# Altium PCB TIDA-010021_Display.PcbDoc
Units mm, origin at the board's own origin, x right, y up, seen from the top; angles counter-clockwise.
Board outline 36.07 x 41.91 mm, 2 copper layers (Top Layer, Bottom Layer), stack 1.575 mm thick; 46 components, 36 nets, 172 pads, 45 vias.
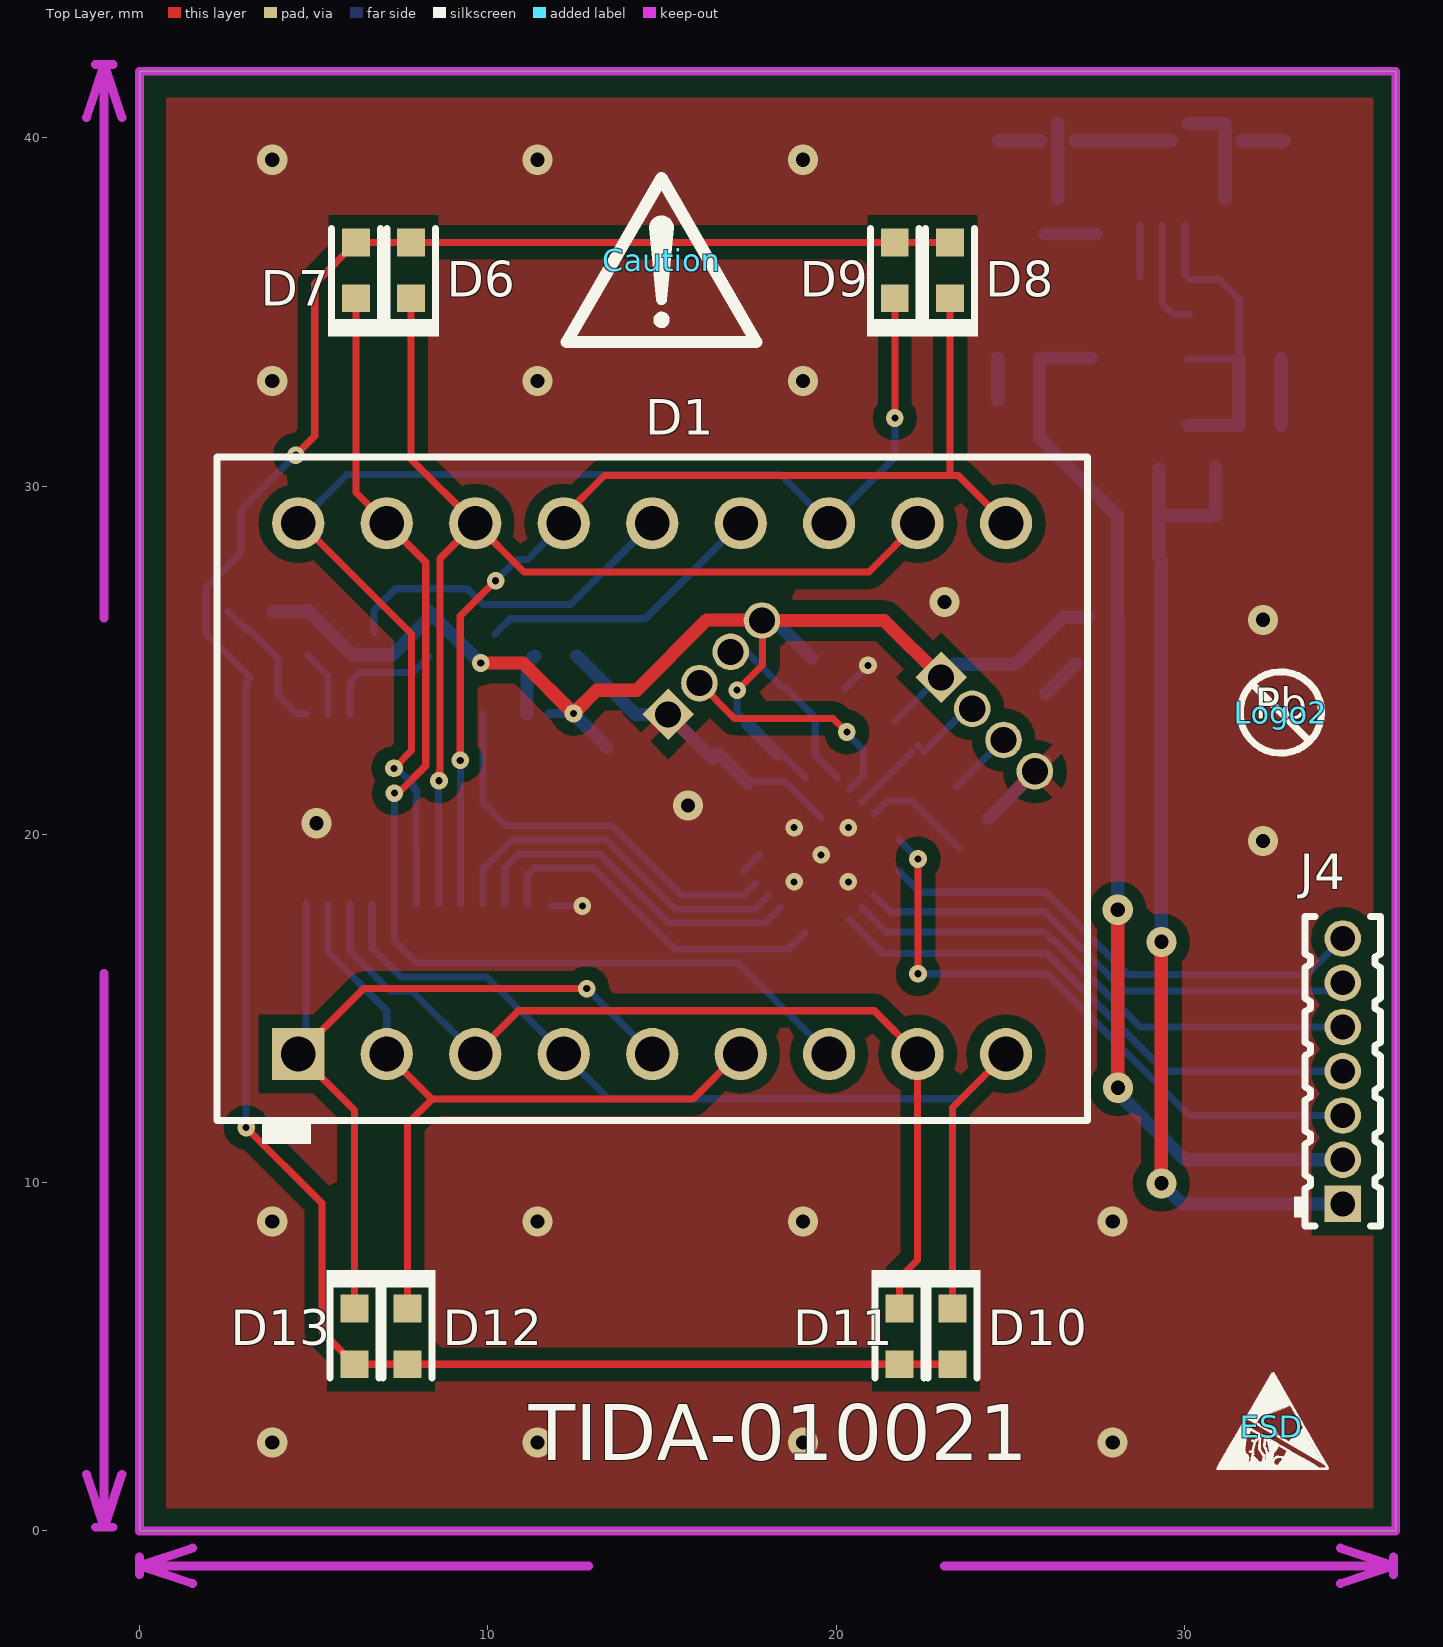
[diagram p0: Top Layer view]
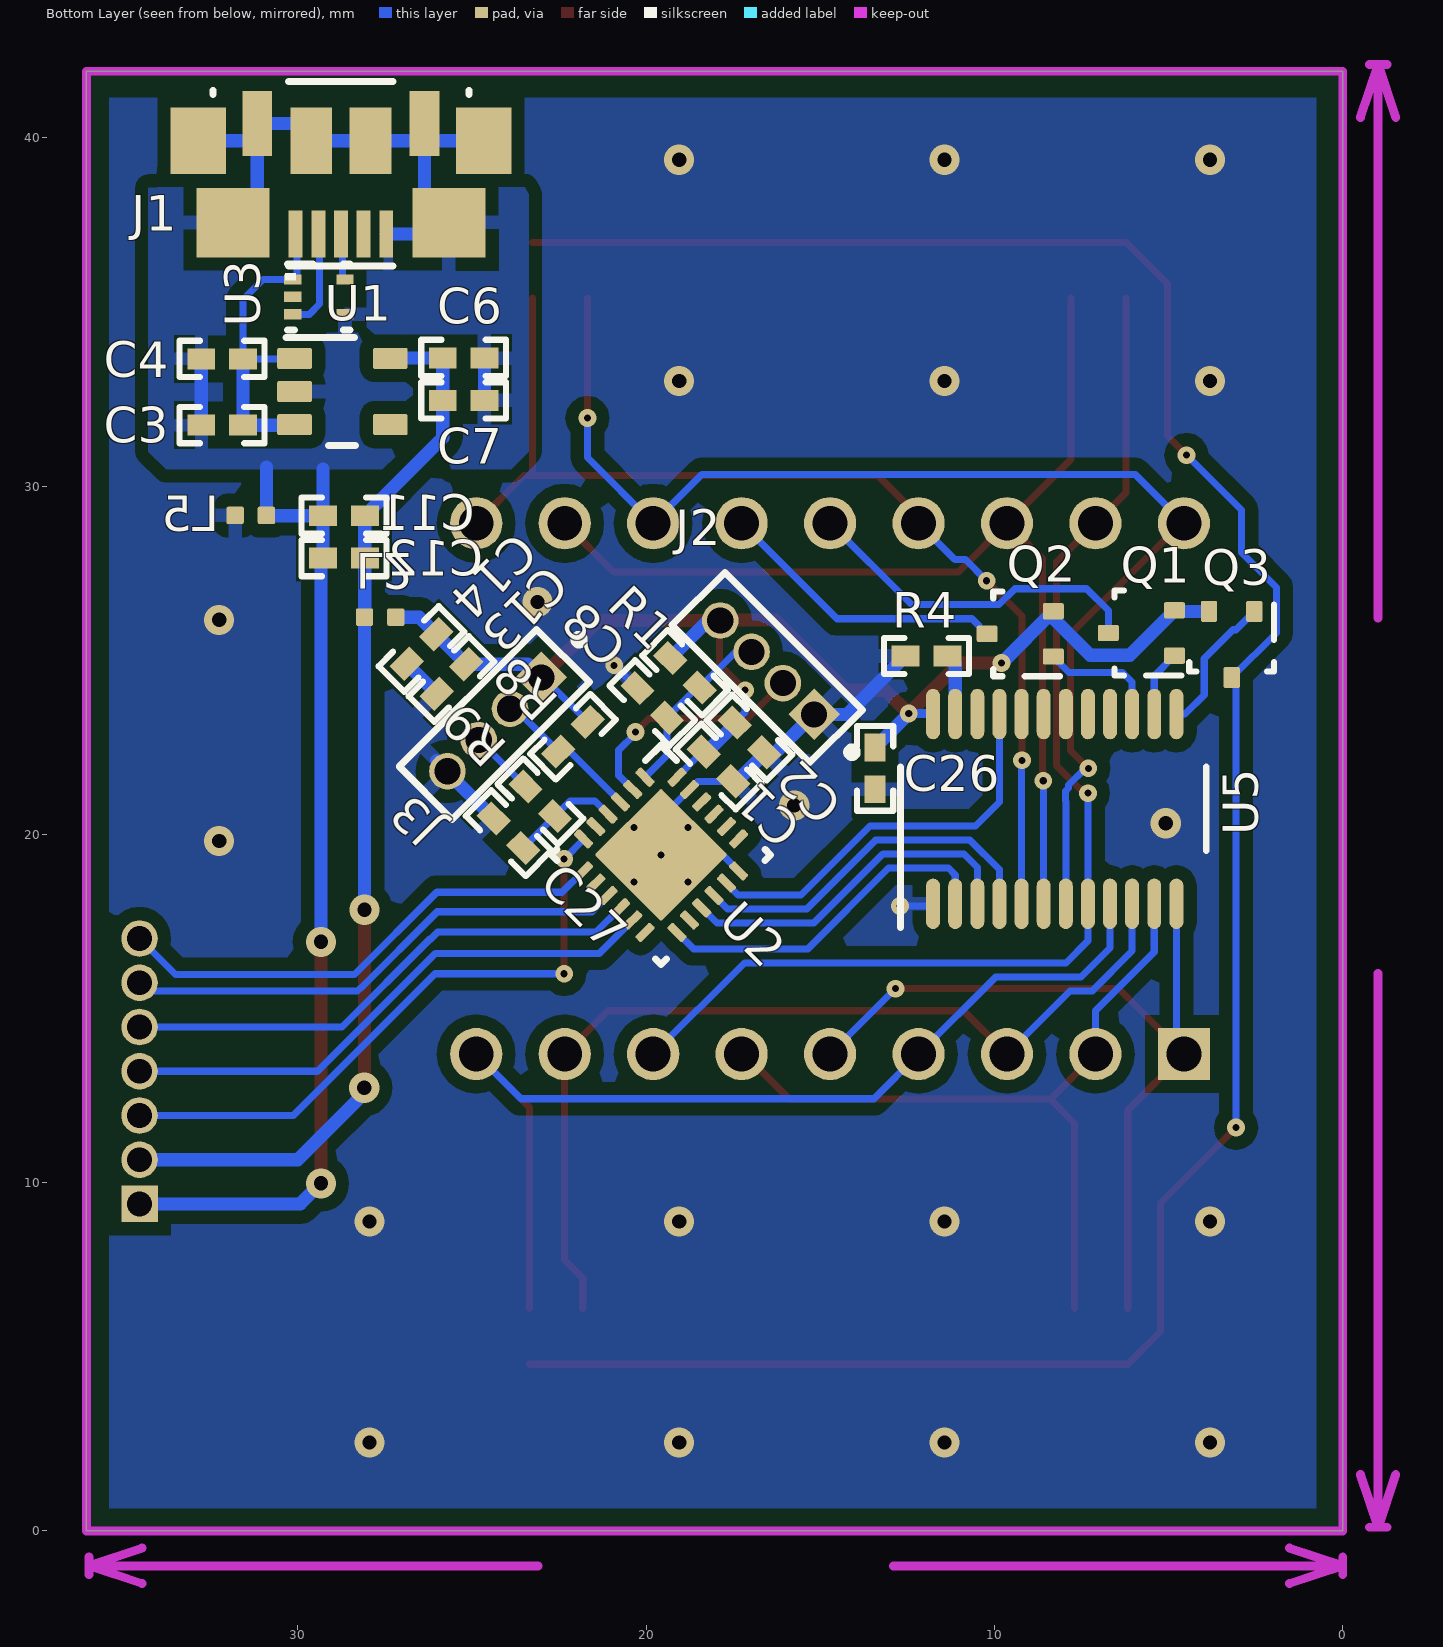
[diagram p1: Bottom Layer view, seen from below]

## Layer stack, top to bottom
Top Solder: solder mask 0.0102, Solder Resist, Dk 3.5
Top Layer: signal copper 0.0356
Dielectric1: core 1.5037, FR-4, Dk 4.8
Bottom Layer: signal copper 0.0356
Bottom Solder: solder mask 0.0102, Solder Resist, Dk 3.5

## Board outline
0,0 0,41.91 36.068,41.91 36.068,0

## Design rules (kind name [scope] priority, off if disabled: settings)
AcuteAngle [All] p1: minimum=4.50000000000000E+0001 checktracksonly=FALSE
AssemblyTestPointUsage [All] p1: valid=2
BoardOutlineClearance BoardOutlineClearance_MountingHoles [OnCopper and InComponentClass('Mounting Holes')] p1: gap=1.016
BoardOutlineClearance BoardOutlineClearance_Poly [OnCopper and IsPoly] p2: gap=0.635
BoardOutlineClearance [OnCopper and Not InComponentClass('Logo') and not InComponentClass('FiducialMark') and not InRegion(1000,500,4000,800) and not InPoly] p3: gap=1.905
Clearance Clearance_Keepouts [((IsTrack Or IsArc) And Not InPoly) And IsFree and IsKeepOut vs ((IsTrack Or IsArc) And Not InPoly) And IsFree and IsKeepOut] p1: gap=0
Clearance Clearance_Poly [InPolygon] p2: gap=0.381
Clearance [All] p3: gap=0.2
ComponentClearance ComponentClearance_MountingHoles_FiducialMarks [InComponentClass('Mounting Holes') vs InComponentClass('FiducialMark')] p1: gap=1.27 collisioncheckmode=3 verticalgap=0.254 showdistances=FALSE
ComponentClearance ComponentClearance_Shunt [InComponentClass('Header') vs InComponentClass('Shunt')] p2: gap=0 collisioncheckmode=3 verticalgap=0 showdistances=FALSE
ComponentClearance ComponentClearance_Logo [InComponentClass('Logo')] p3: gap=1.27 collisioncheckmode=3 verticalgap=0.254 showdistances=FALSE
ComponentClearance ComponentClearance_ScrewToNut [(HasFootprint('NY PMS 440 0025 PH')) vs (HasFootprint('Keystone_1902C'))] p4: gap=0.127 collisioncheckmode=3 verticalgap=0.254 showdistances=FALSE
ComponentClearance ComponentClearance_MountingHoles [InComponentClass('Mounting Holes')] p5: gap=6.35 collisioncheckmode=3 verticalgap=2540 showdistances=FALSE
ComponentClearance ComponentClearance_SmallPassives [HasFootprint('0201*') or HasFootprint('0402*') or HasFootprint('0508') or HasFootprint('0603*') or HasFootprint('0612') or HasFootprint('0805*') or HasFootprint('0815*') or HasFootprint('0830*') or HasFootprint('1206*') or HasFootprint('1210*') or HasFootprint('1808*') or HasFootprint('1812*') or HasFootprint('1825*') or HasFootprint('2010*') or HasFootprint('2220*') or HasFootprint('2225*') or HasFootprint('2512*') or HasFootprint('2728*') or HasFootprint('3518*') vs HasFootprint('0201*') or HasFootprint('0402*') or HasFootprint('0508') or HasFootprint('0603*') or HasFootprint('0612') or HasFootprint('0805*') or HasFootprint('0815*') or HasFootprint('0830*') or HasFootprint('1206*') or HasFootprint('1210*') or HasFootprint('1808*') or HasFootprint('1812*') or HasFootprint('1825*') or HasFootprint('2010*') or HasFootprint('2220*') or HasFootprint('2225*') or HasFootprint('2512*') or HasFootprint('2728*') or HasFootprint('3518*')] p6: gap=0.38 collisioncheckmode=3 verticalgap=0.254 showdistances=FALSE
ComponentClearance ComponentClearance_THtoSMT [IsThruComponent vs IsSMTComponent] p7: gap=1.016 collisioncheckmode=3 verticalgap=0.762 showdistances=FALSE
ComponentClearance ComponentClearance_THtoTH [IsThruComponent vs IsThruComponent] p8: gap=0.762 collisioncheckmode=3 verticalgap=0.762 showdistances=FALSE
ComponentClearance [All] p9: gap=0.762 collisioncheckmode=3 verticalgap=0.254 showdistances=FALSE
DiffPairsRouting [All] p1: maxlimit=2.54 minlimit=0.254 mostfreqgap=0.254 toplayer_minwidth=0.381 toplayer_maxwidth=0.381 toplayer_prefwidth=0.381 bottomlayer_minwidth=0.381 bottomlayer_maxwidth=0.381 bottomlayer_prefwidth=0.381 maxuncoupledlength=25.4
FabricationTestPointUsage TestPointUsage [All] p1: valid=2 allowmultiple=FALSE
FabricationTestpoint Testpoint [All] p1: side=3 testpointundercomponent=TRUE minsize=1.016 maxsize=2.54 preferedsize=1.524 minholesize=0 maxholesize=1.016 preferedholesize=0.813 testpointgrid=0.025 allowsidetop=TRUE allowsidebottom=TRUE usegrid=TRUE gridtolerance=0
FanoutControl Fanout_LCC [IsLCC] p1: bgadir=Out bgaviamode=Centered fanoutstyle=Auto fanoutdirection=Alternating viagrid=0.025 // Fanout_LCC (Default Rule)
FanoutControl Fanout_BGA [IsBGA] p2: bgadir=Out bgaviamode=Centered fanoutstyle=Auto fanoutdirection=Alternating viagrid=0.025 // Fanout_BGA (Default Rule)
FanoutControl Fanout_Default [All] p4: bgadir=Out bgaviamode=Centered fanoutstyle=Auto fanoutdirection=Alternating viagrid=0.025 // Fanout_Default (Default Rule)
FanoutControl Fanout_Small [(CompPinCount < 5)] p5: bgadir=Out bgaviamode=Centered fanoutstyle=Auto fanoutdirection=OutThenIn viagrid=0.025 // Fanout_Small (Default Rule)
HoleSize [All] p1: absolutevalues=TRUE maxlimit=6.375 minlimit=0.2 maxpercent=80.000 minpercent=20.000
MinimumAnnularRing MinimumAnnularRing_ThermalPadVias [IsVia and InAnyComponent] p1: minimumring=0.15
MinimumAnnularRing [All] p2: minimumring=0.203
MinimumSolderMaskSliver MinimumSolderMaskSliver_Logo [InComponentClass('Logo') vs InComponentClass('Logo')] p1: minsoldermaskwidth=0.018
MinimumSolderMaskSliver [All] p2: minsoldermaskwidth=0.1
PlaneClearance [All] p1: clearance=0.381
PlaneConnect [All] p1: planeconnectstyle=Relief reliefexpansion=0.254 reliefentries=4 reliefconductorwidth=0.381 reliefairgap=0.381
PolygonConnect PolygonConnect_Via [IsVia] p1: connectstyle=Direct reliefconductorwidth=0.254 reliefentries=4 polygonreliefangle="90 Angle" airgapwidth=0.254
PolygonConnect [IsComponentPad] p2: connectstyle=Relief reliefconductorwidth=0.381 reliefentries=4 polygonreliefangle="90 Angle" airgapwidth=0.381
RoutingVias ThermalPadVias [IsVia and InAnyComponent] p1: holewidth=0.2 width=0.5 viastyle="Through Hole" minholewidth=0.2 minwidth=0.5 maxholewidth=0.33 maxwidth=0.6
RoutingVias [All] p2: holewidth=0.406 width=0.864 viastyle="Through Hole" minholewidth=0.2 minwidth=0.66 maxholewidth=1.016 maxwidth=1.651
SilkToBoardRegionClearance [Not ((IsComment or IsDesignator) And (Hide <> 'False')) and not InRegion(1000,500,4000,800)] p1:
SilkToSilkClearance SilkToSilkClearance_Pb-FreeLogo [(HasFootprint('Pb-Free_Overlay_Medium') OR HasFootprint('Pb-Free_Overlay_Small')) vs (HasFootprint('Pb-Free_Overlay_Medium') OR HasFootprint('Pb-Free_Overlay_Small'))] p1: silktosilkclearance=0
SilkToSilkClearance [All] p2: silktosilkclearance=0.102
SilkToSolderMaskClearance SilkToComponentPadClearance [(IsPad or IsFill or IsRegion) and InAnycomponent] p1: minsilkscreentomaskgap=0.127 clearancetoexposedcopper=TRUE
SilkToSolderMaskClearance "Silk to Solder Mask Opening" [All] p2: minsilkscreentomaskgap=0.102 clearancetoexposedcopper=FALSE
SolderMaskExpansion [All] p1: expansion=0.05
Width [All] p1: maxlimit=2.54 minlimit=0.152 preferedwidth=0.254 checkconnectedcopper=TRUE
14 further rules are at their usual default settings.

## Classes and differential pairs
component class Header: J2 J3 J4
component class TIDA-010021_Display: C1 C2 C3 C4 C6 C7 C8 C11 C12 C13 C14 C26 C27 D1 D6 D7 D8 D9 D10 D11 D12 D13 J1 J2 J3 J4 L2 L5 Q1 Q2 Q3 R1 R4 R8 R9 U1 U2 U3 U5
component class TIDA-010021_Display_Hardware: Caution ESD Logo2 ZZ1 ZZ2 ZZ3 ZZ4
component class AssemblyNote: ZZ1 ZZ2 ZZ3 ZZ4

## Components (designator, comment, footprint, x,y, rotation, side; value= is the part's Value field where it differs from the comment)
C1 "885012205037" 0402 17.92,21.948 r45 bottom
C2 "CL05A106MP5NUNC" 0402 17.031,22.786 r45 bottom
C3 "885012205037" 0402 32.174,31.75 r0 bottom
C4 "CL05A106MP5NUNC" 0402 32.174,33.655 r0 bottom
C6 "885012205037" 0402 25.24,33.68 r180 bottom
C7 "CL05A106MP5NUNC" 0402 25.24,32.461 r180 bottom
C8 "885012205044" 0402 19.825,23.777 r45 bottom
C11 "885012205037" 0402 28.675,29.151 r0 bottom
C12 "GRM155R61A105KE15D" 0402 28.675,27.931 r0 bottom
C13 "885012205037" 0402 25.588,24.463 r315 bottom
C14 "GRM155R61A105KE15D" 0402 26.45,25.325 r315 bottom
C26 "GRM155R61A105KE15D" 0402 13.424,21.897 r270 bottom
C27 "885012205055" 0402 23.952,20.036 r45 bottom
Caution "CAUTION.  READ USER GUIDE BEFORE USE" IEC_Caution_small 14.986,36.5 r0 top
D1 "LTD-6910HR" LTD-6910H_Red 14.718,21.313 r90 top
D6 "150060RS75000" WL-SMCW_RED 7.798,36.195 r90 top
D7 "150060RS75000" WL-SMCW_RED 6.216,36.195 r90 top
D8 "150060RS75000" WL-SMCW_RED 23.266,36.195 r90 top
D9 "150060RS75000" WL-SMCW_RED 21.684,36.195 r90 top
D10 "150060RS75000" WL-SMCW_RED 23.343,5.588 r270 top
D11 "150060RS75000" WL-SMCW_RED 21.819,5.588 r270 top
D12 "150060RS75000" WL-SMCW_RED 7.696,5.588 r270 top
D13 "150060RS75000" WL-SMCW_RED 6.172,5.588 r270 top
ESD "ESD Susceptible" ESD_Overlay_small 32.512,3 r0 top
J1 "ZX62R-B-5P" Hirose_ZX62R-B-5P 28.762,39.916 r90 bottom
J2 "GRPB041VWVN-RC" Sullins_GRPB041VWVN-RC 16.523,24.793 r45 bottom
J3 "GRPB041VWVN-RC" Sullins_GRPB041VWVN-RC 24.358,23.16 r315 bottom
J4 "FTS-107-01-F-S" Samtec_FTS-107-01-x-S 34.544,13.2 r90 top
L2 "MMZ1005S182ET000" MMZ1005-E 27.635,26.238 r180 bottom
L5 "MMZ1005S182ET000" MMZ1005-E 31.351,29.159 r0 bottom
Logo2 "Pb-Free Symbol" Pb-Free_Overlay_Small 32.766,23.5 r0 top
Q1 "RN2314" SOT-323 5.779,25.783 r0 bottom
Q2 "RN2314" SOT-323 9.258,25.758 r0 bottom
Q3 "RN2314" SOT-323 3.188,25.453 r270 bottom
R1 "RC0402FR-0747KL" 0402 18.885,24.64 r45 bottom
R4 "CRCW040210K0JNED" 0402 11.951,25.123 r180 bottom
R8 "RC0402FR-0747KL" 0402 22.097,22.804 r315 bottom
R9 "RC0402FR-07470RL" 0402 23.037,20.95 r225 bottom
U1 "TLV70233DBVR" DBV0005A_N 28.719,32.715 r180 bottom
U2 "MSP430FR2433IRGER" RGE0024H 19.571,19.414 r225 bottom
U3 "TPD2E001DRLR" DRL0005A 29.396,35.433 r180 bottom
U5 "TLC59283DBQ" DBQ0024A_N 8.268,20.731 r90 bottom
ZZ1 "This Assembly Note is for PCB labels only" AssemblyNoteLabel -3.124,88.189 r0 top
ZZ2 "These assemblies are ESD sensitive, ESD precautions shall be observed." AssemblyNote -3.124,85.423 r0 top
ZZ3 "These assemblies must be clean and free from flux and all contaminants. Use of no clean flux is not acceptable." AssemblyNote -3.124,83.174 r0 top
ZZ4 "These assemblies must comply with workmanship standards IPC-A-610 Class 2, unless otherwise specified." AssemblyNote -3.124,80.924 r0 top

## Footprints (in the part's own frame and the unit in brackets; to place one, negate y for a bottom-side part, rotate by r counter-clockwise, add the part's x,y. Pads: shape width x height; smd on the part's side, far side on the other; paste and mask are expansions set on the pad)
0402 [mm] "0402 from SM-752 data"
  rect 0.8x0.6 smd: 1(-0.6,0) 2(0.6,0)
  silkscreen extent -1.22,-0.52 1.22,0.52, body extent -0.55,-0.3 0.55,0.3, height 0.6
AssemblyNote [mm] "Assembly Note"
AssemblyNoteLabel [mm] "Assembly Note for PCB Labels"
DBQ0024A_N [mm] "SOP, 24-Leads, Body 8.7x3.9mm, Pitch 0.635mm, IPC Medium Density"
  oval 1.45x0.4 smd: 1(-2.725,3.492) 2(-2.725,2.857) 3(-2.725,2.222) 4(-2.725,1.588) 5(-2.725,0.953) 6(-2.725,0.318) 7(-2.725,-0.317) 8(-2.725,-0.952) 9(-2.725,-1.587) 10(-2.725,-2.222) 11(-2.725,-2.857) 12(-2.725,-3.492) 13(2.725,-3.492) 14(2.725,-2.857) 15(2.725,-2.222) 16(2.725,-1.588) 17(2.725,-0.953) 18(2.725,-0.318) 19(2.725,0.317) 20(2.725,0.952) 21(2.725,1.587) 22(2.725,2.222) 23(2.725,2.857) 24(2.725,3.492)
  silkscreen extent -3.4,-4.35 1.2,4.43, body extent -3.01,-4.32 3.01,4.33, height 1.75
DBV0005A_N [mm] "SOT23, 5-Leads, Body 2.9x1.6mm, Pitch 0.95mm, Lead Span 2.8mm, IPC Medium Density"
  rrect17% 1x0.6 smd: 1(-1.375,0.95) 2(-1.375,0) 3(-1.375,-0.95) 4(1.375,-0.95) 5(1.375,0.95)
  silkscreen extent -1.63,-1.55 0.38,1.55, body extent -1.42,-1.46 1.42,1.46, height 1.09
DRL0005A [mm] "SOTFL, 5-Flat Leads, Body 1.2x1.6x0.6mm, Pitch 0.5mm, TI recommended"
  rect 0.5x0.3 smd: 1(-0.75,0.5) 2(-0.75,0) 3(-0.75,-0.5) 4(0.75,-0.5) 5(0.75,0.5)
  silkscreen extent -0.9,-0.95 0.9,0.95, body extent -0.85,-0.85 0.85,0.85, height 0.62
ESD_Overlay_small [mm]
  silkscreen extent -1.58,-1.23 1.62,1.55
Hirose_ZX62R-B-5P [mm] "Hirose"
  rect 1.35x0.4 smd: 1(-2.68,1.3) 2(-2.68,0.65) 3(-2.68,0) 4(-2.68,-0.65) 5(-2.68,-1.3)
  rect 2x2.1 smd: 6(-2.35,-3.1) 7(-2.35,3.1)
  rect 1.9x1.6 smd: 8(0,-4.1) 13(0,4.1)
  rect 1.88x0.85 smd: 9(0.495,-2.4) 12(0.495,2.4)
  rect 1.9x1.2 smd: 10(0,-0.85) 11(0,0.85)
  silkscreen extent -4,-3.67 1.7,3.67, body extent -2.57,-3.48 2.11,3.45, height 2.65
IEC_Caution_small [mm]
  silkscreen extent -2.72,-2.36 2.72,2.35
LTD-6910H_Red [mm] "TH, 18-Leads, Body 25x19.05mm, Pitch 2.54mm"
  rect 1.5x1.5 hole 1: 1(-7.62,10.16)
  round 1.5 hole 1: 2(-7.62,7.62) 3(-7.62,5.08) 4(-7.62,2.54) 5(-7.62,0) 6(-7.62,-2.54) 7(-7.62,-5.08) 8(-7.62,-7.62) 9(-7.62,-10.16) 10(7.62,-10.16) 11(7.62,-7.62) 12(7.62,-5.08) 13(7.62,-2.54) 14(7.62,0) 15(7.62,2.54) 16(7.62,5.08) 17(7.62,7.62) 18(7.62,10.16)
  silkscreen extent -10.2,-12.5 9.53,12.5, body extent -9.53,-12.5 9.52,12.5, height 8.02
MMZ1005-E [mm] "SMD, 2-Leads, Body 1x0.5mm"
  rrect20% 0.5x0.5 smd: 1(-0.45,0) 2(0.45,0)
  body extent -0.53,-0.28 0.53,0.28, height 0.55
Pb-Free_Overlay_Small [mm]
  silkscreen extent -1.16,-1.17 1.17,1.17
RGE0024H [mm] "QFN, 24-Leads, Body 4x4mm, Pitch 0.5mm, Thermal Pad 2.7x2.7mm, TI Recommended"
  rrect42% 0.6x0.24 smd: 1(-1.9,1.25) 2(-1.9,0.75) 3(-1.9,0.25) 4(-1.9,-0.25) 5(-1.9,-0.75) 6(-1.9,-1.25) 13(1.9,-1.25) 14(1.9,-0.75) 15(1.9,-0.25) 16(1.9,0.25) 17(1.9,0.75) 18(1.9,1.25)
  rrect42% 0.24x0.6 smd: 7(-1.25,-1.9) 8(-0.75,-1.9) 9(-0.25,-1.9) 10(0.25,-1.9) 11(0.75,-1.9) 12(1.25,-1.9) 19(1.25,1.9) 20(0.75,1.9) 21(0.25,1.9) 22(-0.25,1.9) 23(-0.75,1.9) 24(-1.25,1.9)
  rrect8% 1.19x1.19 on Bottom Paste: 25(-0.695,-0.695) 25(-0.695,0.695) 25(0.695,0.695) 25(0.695,-0.695)
  rrect4% 2.7x2.7 smd paste-1.35: 25(0,0)
  silkscreen extent -2.22,-2.23 2.23,2.23, body extent -2.08,-2.08 2.08,2.07, height 1.01
Samtec_FTS-107-01-x-S [mm] "Header, 1.27 mm, 7x1, TH"
  rect 1.05x1.05 hole 0.71: 1(-3.81,0)
  round 1.05 hole 0.71: 2(-2.54,0) 3(-1.27,0) 4(0,0) 5(1.27,0) 6(2.54,0) 7(3.81,0)
  silkscreen extent -4.45,-1.08 4.45,1.4, body extent -4.44,-1.08 4.45,1.08, height 3.91
SOT-323 [mm] "Diodes Inc recommended land pattern.  2016-02-24"
  rrect21% 0.6x0.47 smd: 1(-0.95,0.65) 2(-0.95,-0.65) 3(0.95,0)
  silkscreen extent -1.14,-1.22 0.77,1.22, body extent -1.13,-1.13 1.12,1.12, height 1.13
Sullins_GRPB041VWVN-RC [mm] "TH, Header, 1.27 mm, 4x1, Straight"
  rect 1.05x1.05 hole 0.75: 1(-1.905,0)
  round 1.05 hole 0.75: 2(-0.635,0) 3(0.635,0) 4(1.905,0)
  silkscreen extent -3.54,-1.07 2.79,1.07, body extent -2.79,-1.07 2.79,1.07, height 4.3
WL-SMCW_RED [mm] "WURTH"
  rect 0.8x0.8 smd: 1(-0.8,0) 2(0.8,0)
  silkscreen extent -1.9,-0.8 1.2,0.8, body extent -0.85,-0.45 0.85,0.45, height 0.8

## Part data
C1 C3 C6 C11 C13: "CAP, CERM, 0.1 μF, 16 V, +/- 10%, X7R, 0402"
C2 C4 C7: library part CMP-0006339-1, "CAP, CERM, 10 uF, 10 V, +/- 20%, X5R, 0402"
C8: "CAP, CERM, 1000 pF, 25 V, +/- 10%, X7R, 0402"
C12 C14 C26: "CAP, CERM, 1 μF, 10 V, +/- 10%, X5R, 0402"
C27: "CAP, CERM, 100 pF, 50 V, +/- 10%, X7R, 0402"
Caution: library part IEC_Caution, "IEC 61010-1 Caution Warning"
D1: "LED, Red, TH"
D6 D7 D8 D9 D10 D11 D12 D13: "LED, Red, SMD"
ESD: library part ESD_Susceptible, "ESD Susceptible Symbol"
J1: "Connector, Receptacle, Micro-USB Type B, SMT"
J2 J3: "Header, 50mil, 4x1, Gold, TH"
J4: library part CMP-0075532-1, "Header, 1.27mm, 7x1, Gold, TH"
L2 L5: library part CMP-0080017-1, "Inductor, Ferrite Bead, Ferrite, 0.2 A, 2.1 ohm, SMD"
Logo2: library part Pb-Free
Q1 Q2 Q3: library part "PDTA124EU,115, NXP Semiconductor", "Transistor, PNP, 50 V, 0.1 A, SOT-323"
R1 R8: "RES, 47.0 k, 1%, 0.0625 W, 0402"
R4: "RES, 10 k, 5%, 0.063 W, 0402"
R9: "RES, 470, 1%, 0.063 W, 0402"
U1: "Single Output LDO, 300 mA, Fixed 3.3 V Output, 2 to 5.5 V Input, with Low IQ, 5-pin SOT-23 (DBV), -40 to 125 degC, Green (RoHS & no Sb/Br)"
U2: "MSP430FR2433 16 MHz Ultra-Low-Power Microcontroller with 16 KB FRAM, 4 KB RAM, 19 IO, 4 Timers, RGE0024H (VQFN-24)"
U3: "Low-Capacitance + / - 15 kV ESD-Protection Array for High-Speed Data Interfaces, 2 Channels, -40 to +85 degC, 5-pin SOT (DRL), Green (RoHS & no Sb/Br)"
U5: library part TLC59282DBQ, "16-Channel Constant Current LED Driver with 4-Channel Grouped Delay, 3 to 5.5 V, -40 to 85 degC, 24-pin SOP (DBQ24), Green (RoHS & no Sb/Br)"
ZZ1: library part AssemblyNoteLabel
ZZ2 ZZ3 ZZ4: library part AssemblyNote

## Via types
v1: diameter 0.864, hole 0.406, Top Layer to Bottom Layer, 23 vias
v2: diameter 0.508, hole 0.203, Top Layer to Bottom Layer, 17 vias
v3: diameter 0.5, hole 0.2, Top Layer to Bottom Layer, 5 vias

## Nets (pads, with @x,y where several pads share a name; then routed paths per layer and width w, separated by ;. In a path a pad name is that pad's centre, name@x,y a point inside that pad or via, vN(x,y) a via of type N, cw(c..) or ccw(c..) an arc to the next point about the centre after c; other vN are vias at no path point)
A: D1.11 D1.16 D6.1 U5.6 | length 32.4
  Top Layer w0.203: D6.1 7.798,30.773 D1.16 ; v2(8.598,21.542) 8.598,21.784 8.62,21.806 8.62,27.915 D1.16 ; D1.11 20.941,27.536 11.035,27.536 D1.16
  Bottom Layer w0.203: U5.6 v2@8.585,21.529
B: D1.10 D1.15 D8.1 U5.5 | length 31.4
  Top Layer w0.203: v2(9.208,22.126) 9.208,26.266 v2(10.224,27.282) ; D1.15 12.178,29.135 13.348,30.305 21.882,30.305 23.266,30.305 ; D8.1 23.266,30.305 ; D1.10 23.507,30.305 23.266,30.305
  Bottom Layer w0.203: v2(9.208,22.126) 9.22,22.113 U5.5 ; v2(10.224,27.282) 10.833,27.892 11.137,27.892 D1.15
BLANK: U2.17 U5.21 | length 11.6
  Bottom Layer w0.203: U5.21 9.855,20.927 10.539,20.243 13.574,20.243 15.555,18.262 17.358,18.262 U2.17
C: D1.3 D1.8 D11.1 U5.10 | length 27.4
  Top Layer w0.203: D1.3 10.883,14.938 21.094,14.938 D1.8 22.338,7.784 21.819,7.264 D11.1
  Bottom Layer w0.203: U5.10 6.045,16.652 7.191,15.506 7.825,15.506 D1.3
COM1: Q1.1 U5.14 | length 1.9
  Bottom Layer w0.203: Q1.1 5.41,24.552 U5.14
COM2: Q2.1 U5.15 | length 3.5
  Bottom Layer w0.203: U5.15 6.045,24.374 6.325,24.653 7.854,24.653 Q2.1
COM3: Q3.1 U5.13 | length 4.1
  Bottom Layer w0.203: Q3.1 3.065,25.876 3.153,25.876 3.975,25.054 3.975,24.005 4.524,23.456 U5.13
D: D1.2 D1.6 D12.1 U5.11 | length 22.5
  Top Layer w0.203: D1.2 8.394,12.398 ; D12.1 7.696,11.7 8.394,12.398 ; D1.6@17.183,13.693 15.888,12.398 8.394,12.398
  Bottom Layer w0.203: U5.11 5.41,16.627 7.098,14.939 D1.2
DIG1: D1.14 Q1.3 | length 10.1
  Bottom Layer w0.203: Q1.3 6.729,26.429 7.353,27.053 9.411,27.053 9.868,26.596 12.381,26.596 D1.14
DIG2: D1.13 Q2.3 | length 8.4
  Bottom Layer w0.203: Q2.3 10.643,26.193 14.518,26.193 D1.13
DIG3: D6.2 D7.2 D8.2 D9.2 D10.2 D11.2 D12.2 D13.2 Q3.3 | length 70.1
  Top Layer w0.203: v2(3.061,11.585) 5.232,9.413 5.232,5.728 D13.2 D12.2 D11.2 D10.2 ; v2(4.484,30.89) 5.029,31.435 5.029,35.808 D7.2 D6.2 D9.2 D8.2
  Bottom Layer w0.203: v2@3.086,11.61 v2(3.061,11.585) 3.061,24.376 Q3.3 1.905,25.786 1.905,27.091 2.908,28.095 2.908,29.314 v2(4.484,30.89)
DP: D1.4 D1.9 D10.1 U5.9 | length 29.7
  Top Layer w0.203: D10.1 23.343,12.157 D1.9
  Bottom Layer w0.203: U5.9 6.68,16.741 7.512,15.909 9.962,15.909 D1.4 13.462,12.41 23.595,12.41 D1.9
E: D1.1 D1.5 D13.1 U5.12 | length 23.8
  Top Layer w0.203: D13.1 6.172,12.079 D1.1 6.438,15.573 v2(12.839,15.573)
  Bottom Layer w0.203: D1.1@4.775,13.91 U5.12 ; v2(12.839,15.573) D1.5
F: D1.12 D1.18 D9.1 U5.7 | length 36.7
  Top Layer w0.203: D1.18@4.558,28.805 D1.18 ; D1.18@4.686,28.805 4.582,28.7 4.868,28.7 7.811,25.758 7.811,22.405 v2(7.303,21.897) ; v2(21.684,31.953) D9.1
  Bottom Layer w0.203: D1.18 5.955,30.33 18.401,30.33 D1.12 21.684,30.819 v2(21.684,31.953) ; v2(7.303,21.897) 7.39,21.897 7.871,21.416 7.871,21.329 7.96,21.24 7.96,20.956 7.941,20.937 7.941,19.608 7.95,19.598 U5.7
G: D1.7 D1.17 D7.1 U5.8 | length 33.6
  Top Layer w0.203: D7.1 6.216,29.815 D1.17 8.217,27.814 8.217,21.973 7.43,21.186 v2(7.315,21.186)
  Bottom Layer w0.203: v2(7.315,21.186) U5.8 7.315,16.945 7.948,16.312 17.179,16.312 D1.7 D1.7@19.85,13.745
GP1: J4.3 U2.6 | length 18
  Top Layer w0.203: v2(22.352,16) v2(22.352,19.296)
  Bottom Layer w0.203: U2.6@21.798,19.85 v2(22.352,19.296) ; v2(22.352,16) 26.062,16 30.132,11.93 J4.3
GP2: J4.4 U2.11 | length 15.9
  Bottom Layer w0.203: U2.11 21.338,16.586 26.046,16.586 29.433,13.2 ; 29.495,13.2 J4.4
IOVDD: C1.2 C2.2 C13.1 C14.1 C26.1 J2.4 J3.1 L2.2 Q1.2 Q2.2 Q3.2 R1.2 R8.1 U2.24 U5.24 | length 39.9
  Top Layer w0.203: v2@17.167,24.142 17.887,24.863 J2.4@17.887,26.14
  Top Layer w0.381: v2(9.797,24.92) 11.011,24.92 v2(12.459,23.472) 13.129,24.142 14.274,24.142 16.289,26.157 17.887,26.157 J2.4@17.887,26.14 ; v2(17.158,24.142) v2@17.167,24.142 ; J2.4 J2.4@17.887,26.14 ; J3.1 21.378,26.14 J2.4@17.887,26.14
  Bottom Layer w0.203: Q2.2@8.308,26.202 Q2.2 ; v2(17.158,24.142) 17.158,23.508 C2.2 ; C1.2@18.434,22.319 U2.24 ; R8.1 22.952,24.507 J3.1
  Bottom Layer w0.254: U5.24 11.776,23.472 v2(12.459,23.472)
  Bottom Layer w0.381: Q3.2 Q1.2@4.798,26.403 ; Q1.2 6.117,25.145 7.252,25.145 Q2.2@8.308,26.202 ; Q2.2 v2(9.797,24.92) ; v2@12.459,23.462 C26.1 ; C2.2@17.446,23.183 C1.2@18.31,22.319 ; J2.4@17.718,25.987 J2.4@17.995,25.987 ; J2.4 18.234,26.14 R1.2 ; J3.1 23.391,24.887 C13.1 26.515,26.238 L2.2@27.236,26.238
IOVSS: C1.1 C2.1 C8.2 C13.2 C14.2 C26.2 C27.2 J2.1 J3.4 L5.2 R4.1 U2.18 U2.23 U2.25@19.571,19.414 U5.1 | length 15.1
  Bottom Layer w0.203: U5.1@11.822,17.944 v2(12.713,17.944) ; C2.1@16.445,22.182 C2.1@16.598,22.334 ; U2.18 U2.25@17.803,19.414 ; C1.1 18.522,21.524 U2.23 U2.25@19.571,20.475 ; C8.2 20.265,24.201 v2(20.917,24.853)
  Bottom Layer w0.381: R4.1 14.228,23.446 J2.1 15.181,23.446 C2.1@16.445,22.182 ; C2.1@16.598,22.334 C1.1@17.461,21.47 ; C27.2 25.705,21.789 J3.4 J3.4@26.012,22.12 ; C13.2 C14.2
  other v1: 3.81,2.54 11.43,2.54 19.05,2.54 27.94,2.54 3.81,8.89 11.43,8.89 19.05,8.89 27.94,8.89 32.258,19.812 5.08,20.32 15.748,20.828 32.258,26.162 23.114,26.67 3.81,33.02 11.43,33.02 19.05,33.02 3.81,39.37 11.43,39.37 19.05,39.37
  other v3: 18.793,18.636 20.349,18.636 19.571,19.414 18.793,20.192 20.349,20.192
LAT: U2.16 U5.4 | length 10.5
  Bottom Layer w0.203: U5.4 9.855,18.989 10.706,19.84 13.407,19.84 15.388,17.859 17.662,17.859 U2.16
NetJ1_2: J1.2 U3.3 | length 3.2
  Bottom Layer w0.203: J1.2@29.373,37.502 29.373,35.227 29.667,34.933 U3.3
NetJ1_3: J1.3 U3.5 | length 1.5
  Bottom Layer w0.203: U3.5@28.723,36.01 J1.3@28.723,37.502
NetJ3_3: J3.3 R9.1 | length 1.9
  Bottom Layer w0.203: R9.1 J3.3@24.798,22.711
  Bottom Layer w0.381: J3.3@24.798,22.711 J3.3
NetR4_2: R4.2 U5.23 | length 1.8
  Bottom Layer w0.381: U5.23 11.125,24.897 R4.2
RXD: C27.1 R9.2 U2.4 | length 3.1
  Bottom Layer w0.203: U2.4 21.467,20.956 22.182,20.956 R9.2 C27.1
SBWTCLK: J2.2 U2.2 | length 6.9
  Top Layer w0.203: J2.2 17.085,23.332 19.914,23.332 v2(20.307,22.939)
  Bottom Layer w0.203: v2(20.307,22.939) 20.266,22.897 20.266,22.885 20.324,22.885 20.788,22.421 20.788,21.691 U2.2
SBWTDIO: C8.1 J2.3 R1.1 U2.1 | length 5.1
  Bottom Layer w0.203: J2.3 17.435,25.242 R1.1 ; R1.1@18.537,24.216 C8.1 19.401,22.271 U2.1
SCL: J4.5 U2.10 | length 15.2
  Bottom Layer w0.203: U2.10 21.436,17.196 25.984,17.196 26.191,16.989 26.213,16.989 28.733,14.47 J4.5
SCLK: U2.15 U5.3 | length 10.1
  Bottom Layer w0.203: U5.3 10.49,19.054 10.873,19.436 13.204,19.436 15.185,17.455 17.966,17.455 U2.15
SDA: J4.6 U2.9 | length 14.4
  Bottom Layer w0.203: U2.9 21.558,17.78 25.998,17.78 28.205,15.573 28.216,15.573 28.29,15.5 J4.6@34.304,15.5
SIN: U2.13 U5.2 | length 10.1
  Bottom Layer w0.203: U5.2 11.125,18.836 11.322,19.033 13.037,19.033 15.354,16.716 18.64,16.716 U2.13
TXD: J3.2 R8.2 U2.3 | length 4.2
  Bottom Layer w0.203: U2.3 R8.2@22.183,22.38 ; R8.2@22.351,22.55 R8.2 23.751,23.609 J3.2
USB_5V: C3.1 C4.1 J1.1 U1.1 U1.3 U3.1 | length 9.7
  Bottom Layer w0.203: U3.1@30.023,36.056 J1.1@30.023,37.502 ; U1.1@30.105,33.655 C4.1 31.574,35.363 31.004,35.933 U3.1
  Bottom Layer w0.381: U1.3@30.11,31.75 C3.1 C4.1
VDD_3V3: C6.1 C7.1 C11.1 C12.1 J4.2 L2.1 U1.5 | length 30.6
  Top Layer w0.381: v1@28.085,12.733 v1(28.085,17.838)
  Bottom Layer w0.381: U1.5@27.329,33.68 C6.1 C7.1 25.84,31.386 C11.1 C12.1 L2.1@28.075,26.249 ; v1(28.085,17.838) L2.1 ; v1@28.092,12.573 30.005,10.66 J4.2
  other v1: 28.092,12.725
VSS_IN: C3.2 C4.2 C6.2 C7.2 C11.2 C12.2 J1.5 J1.6 J1.7 J1.8 J1.9 J1.10 J1.11 J1.12 J1.13 J4.1 L5.1 U1.2 U3.4 | length 43.9
  Top Layer w0.381: v1(29.337,9.982) v1(29.337,16.916)
  Bottom Layer w0.381: C7.2 C6.2 ; J1.8 25.867,39.916 ; J1.6@25.992,37.236 J1.5 ; J1.6@26.362,38.266 J1.9 ; 26.857,39.916 J1.10 J1.11 ; 29.275,30.486 C11.2 ; v1(29.337,9.982) 29.929,9.39 J4.1 ; v1(29.337,16.916) 29.337,27.869 C12.2 C11.2 ; J1.11@30.107,40.411 J1.12 J1.7@31.162,38.266 ; L5.1@30.751,29.151 C11.2 ; L5.1 30.901,30.538 ; 31.657,39.916 J1.13 ; C3.2 C4.2
VSYNC_RST: J4.7 U2.7 | length 14.4
  Bottom Layer w0.203: U2.7 22.414,18.339 26.01,18.339 28.372,15.977 33.511,15.977 J4.7
pads on no net: J1.4 U1.4 U2.5 U2.8 U2.12 U2.14 U2.19 U2.20 U2.21 U2.22 U2.25@18.588,19.414 U2.25@19.571,18.431 U2.25@19.571,20.397 U2.25@20.554,19.414 U3.2 U5.16 U5.17 U5.18 U5.19 U5.20 U5.22

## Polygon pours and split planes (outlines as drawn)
IOVSS on Top Layer "TOP_LAYER_IOVSS_P000" (solid, remove dead copper, pour order 0): 0.762,41.148 35.56,41.148 35.56,0.508 0.762,0.508 0.762,41.148
IOVSS on Bottom Layer "BOTTOM_LAYER_IOVSS_P006" (solid, remove dead copper, pour order 6): 0.762,41.148 35.421,41.148 35.421,0.647 0.762,0.647 0.762,41.148
VSS_IN on Bottom Layer "BOTTOM_LAYER_VSS_IN_P004" (solid, remove dead copper, pour order 4): 23.368,40.64 34.29,40.64 34.29,30.988 33.782,30.48 23.876,30.48 23.368,30.988

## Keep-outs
Keep-Out Layer:
  lines w0.254: -1.524,1.63 -1.016,0.106 ; -1.524,40.582 -1.016,42.106 ; -1.27,0.106 -0.762,0.106 ; -1.27,42.106 -0.762,42.106 ; -1.016,16.002 -1.016,0.106 ; -1.016,26.21 -1.016,42.106 ; -0.508,1.63 -1.016,0.106 ; -0.508,40.582 -1.016,42.106 ; 0,-1.254 0,-0.746 ; 1.524,-1.508 0,-1 ; 1.524,-0.492 0,-1 ; 12.896,-1 0,-1 ; 23.104,-1 36,-1 ; 34.476,-1.508 36,-1 ; 34.476,-0.492 36,-1 ; 36,-1.254 36,-0.746 ; 0,0 0,41.91 36.068,41.91 36.068,0 0,0
  text "42 (mm)" at -0.102,16.256 h1.52 r90
  text "36 (mm)" at 13.15,-1.914 h1.52
  text ".Layer_Name" at 6.833,-33.642 h1.52

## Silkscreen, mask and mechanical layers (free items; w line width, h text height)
Top Overlay:
  text "TIDA-010021" at 11.176,1.5 h2.75
  text ".Layer_Name" at 6.833,-33.642 h1.52
Bottom Overlay:
  text ".Layer_Name" at 6.833,-33.642 h1.52
Top Paste:
  text ".Layer_Name" at 6.833,-33.642 h1.52
Bottom Paste:
  text "This document can handle board shapes up to 7.9in x 10in, although" at 146.355,52.299 h1.52
  text "our panel vendors top out at 7in x 10in." at 146.355,49.147 h1.52
  text "To re-size the board shape, do the following:" at 147.752,45.996 h1.52
  text "Select lines on M1 Board Outline and delete (easy in single layer mode...shift+s)" at 149.276,42.845 h1.52
  text "Draw a rectangle using lines (example will be for a 4\" x 6\" board" at 149.276,39.694 h1.52
  text "Enter Place Line mode (keyboard pl)" at 154.61,36.543 h1.52
  text "keyboard jo to jump to origin, hit enter" at 154.61,33.392 h1.52
  text "keyboard jl to jump to location, set x to 6000, hit enter twice" at 154.61,30.241 h1.52
  text "keyboard jl to jump to location, set x to 6000 and y to 4000, hit enter twice" at 154.61,27.09 h1.52
  text "keyboard jl to jump to location, set x to 0 and y to 4000, hit enter twice" at 154.61,23.939 h1.52
  text "keyboard jo to jump to origin, hit enter" at 154.61,20.788 h1.52
  text "Hit ESC twice to exit place line mode" at 154.61,17.637 h1.52
  text "Select lines on M1 Board Outline" at 149.276,13.978 h1.52
  text "Menu Design|Board Shape|Define from Selected Objects (keyboard dsd)" at 149.276,11.334 h1.52
  text "If you re-size the board, don't forget to move the drill table strings on the" at 146.355,3.226 h1.52
  text "Drill Drawing Layer...they should be just to the right of your board shape" at 151.257,0.533 h1.52
  text ".Layer_Name" at 6.833,-33.642 h1.52
Top Solder:
  text ".Layer_Name" at 6.833,-33.642 h1.52
  text ".Layer_Name" at 6.833,-33.642 h1.52
Bottom Solder:
  text ".Layer_Name" at 6.833,-33.642 h1.52
M1 Board Outline:
  circle w0.006: c-13,-3 r0.003
  circle w0.006: c1.5,0 r0.003
  circle w0.006: c1,0 r0.003
  circle w0.006: c-13,-3 r0.003
  lines w0.254: -7.823,-11.836 -7.823,75.794 117.907,75.794 117.907,-11.836 -7.823,-11.836
  text ".Layer_Name" at 6.833,-33.642 h1.52
M2 Board Dimensions:
  rectangle: -7.823,-18.821 -4.648,-15.646
  rectangle: -4.648,-21.996 4.877,-18.821
  lines w0.178: -7.823,-18.821 17.577,-18.821 ; -4.648,-21.996 -4.648,-15.646 ; -1.473,-21.996 -1.473,-15.646 ; 4.877,-21.996 4.877,-15.646 ; 11.227,-21.996 11.227,-15.646 ; -7.823,-21.996 17.577,-21.996 17.577,-15.646 -7.823,-15.646 -7.823,-21.996
  text ".Layer_Name" at 6.833,-33.642 h1.52
M3 3D STEP Top:
  text ".Layer_Name" at 6.833,-33.642 h1.52
M4 3D STEP Bottom:
  text ".Layer_Name" at 6.833,-33.642 h1.52
M5 Assembly Top:
  lines w0.254: -15.24,-35.463 152.4,-35.463 ; -15.24,-30.298 152.451,-30.298 ; -15.24,-25.133 -15.24,-40.627 86.487,-40.627 152.451,-40.627 152.451,-25.133 -15.227,-25.133 -15.227,-40.627 24.79,-40.627 ; 47.371,-40.627 47.371,-25.133 ; 79.553,-30.298 79.553,-25.133 ; 100.889,-30.298 100.889,-25.133 ; 116.688,-40.792 116.688,-35.64
  text "COMPONENTS MARKED 'DNP' SHOULD NOT BE POPULATED." at 21.476,-19.926 h1.52
  text "ASSEMBLY VARIANT:" at 21.463,-22.86 h1.52
  text ".VariantName" at 47.777,-22.86 h1.52
  text "PCB VIEWED FROM TOP SIDE" at -13.627,-28.49 h1.52
  text "BOARD #:" at 49.276,-28.49 h1.52
  text ".PRJ_Number" at 63.132,-28.49 h1.52
  text "REV:" at 84.582,-28.49 h1.52
  text ".PCB_Rev" at 91.986,-28.49 h1.52
  text "SVN REV:" at 105.867,-28.49 h1.52
  text ".VersionControl_RevNumber" at 118.72,-28.49 h1.52
  text "TID #:" at 49.276,-33.655 h1.52
  text ".TID" at 63.132,-33.655 h1.52
  text "PLOT NAME =" at -13.627,-38.871 h1.52
  text ".plot_File_Name" at 6.833,-38.871 h1.52
  text "GENERATED    :" at 49.327,-38.871 h1.52
  text ".Print_Date" at 71.412,-38.871 h1.52
  text ".Print_Time" at 89.929,-38.871 h1.52
  text "TEXAS INSTRUMENTS" at 122.047,-38.871 h1.52
M6 Assembly Bottom:
  lines w0.254: -15.253,-30.311 152.438,-30.311 ; -15.202,-35.475 152.438,-35.475 ; 20.511,-40.805 20.511,-35.653 ; 36.309,-30.311 36.309,-25.146 ; 57.645,-30.311 57.645,-25.146 ; 89.827,-40.64 89.827,-25.146 ; 112.408,-40.64 152.425,-40.64 152.425,-25.146 -15.253,-25.146 -15.253,-40.64 50.711,-40.64 152.438,-40.64 152.438,-25.146
  text "PCB VIEWED FROM BOTTOM SIDE" at 95.25,-13.97 h1.52 r180
  text "COMPONENTS MARKED 'DNP' SHOULD NOT BE POPULATED." at 147.168,-19.914 h1.52
  text ".VariantName" at 120.65,-22.86 h1.52
  text "ASSEMBLY VARIANT:" at 147.041,-22.86 h1.52
  text ".VersionControl_RevNumber" at 18.479,-28.503 h1.52
  text "SVN REV:" at 31.331,-28.503 h1.52
  text ".PCB_Rev" at 45.212,-28.503 h1.52
  text "REV:" at 52.616,-28.503 h1.52
  text ".PRJ_Number" at 74.066,-28.503 h1.52
  text "BOARD #:" at 87.922,-28.503 h1.52
  text ".TID" at 74.066,-33.668 h1.52
  text "TID #:" at 87.922,-33.668 h1.52
  text "TEXAS INSTRUMENTS" at 15.151,-38.883 h1.52
  text ".Print_Time" at 47.269,-38.883 h1.52
  text ".Print_Date" at 65.786,-38.883 h1.52
  text "GENERATED    :" at 87.871,-38.883 h1.52
  text ".plot_File_Name" at 130.365,-38.883 h1.52
  text "PLOT NAME =" at 150.825,-38.883 h1.52
M9 Title Sheet:
  drawing of 57 lines, arcs and shapes, not listed
  text "1" at 10.969,192.291 h1.78
  text "2" at 74.358,192.291 h1.78
  text "3" at 137.588,192.291 h1.78
  text "4" at 201.257,192.291 h1.78
  text "5" at 264.731,192.291 h1.78
  text "6" at 328.358,192.291 h1.78
  text "A" at -18.402,163.258 h1.78
  text "A" at 357.518,163.258 h1.78
  text "B" at -18.402,102.806 h1.78
  text "B" at 357.518,102.806 h1.78
  text "C" at -18.402,42.481 h1.78
  text "C" at 357.518,42.481 h1.78
  text "PROJECT TITLE:" at 280.302,-4.788 h1.14
  text ".PRJ_Title" at 281.572,-8.174 h1.78
  text "DESIGNED FOR:" at 280.302,-12.433 h1.14
  text ".PRJ_Customer" at 281.572,-15.989 h1.78
  text "D" at -18.402,-17.716 h1.78
  text "D" at 357.518,-17.716 h1.78
  text "FILE NAME:" at 280.302,-20.053 h1.14
  text ".PCB_File_Name_No_Path" at 281.572,-23.101 h1.78
  text "Texas Instruments (TI) and/or its licensors do not warrant the accuracy or completeness of this specification" at 154.076,-27.212 h1.14
  text "ENGINEER:" at 280.302,-27.419 h1.14
  text "LAYOUT BY:" at 318.529,-27.419 h1.14
  text "or any information contained therein. TI and/or its licensors do not warrant that this design will meet" at 152.934,-30.074 h1.14
  text ".PRJ_Engineer" at 281.572,-31.356 h1.78
  text ".PCB_Layout" at 319.811,-31.356 h1.78
  text "the specifications, will be suitable for your application or fit for any particular purpose, or will operate in" at 152.934,-32.935 h1.14
  text ".Layer_Name" at 6.833,-33.642 h1.52
  text "ALTIUM DESIGNER VERSION:" at 318.529,-35.293 h1.14
  text "an implementation. TI and/or its licensors do not warrant that the design is production worthy. You should" at 152.934,-35.797 h1.14
  text "completely validate and test your design implementation to confirm the system functionality for your application." at 154.076,-38.659 h1.14
  text ".print_Scale" at 281.572,-38.68 h1.78
  text ".Application_BuildNumber" at 319.811,-38.68 h1.78
  text "1" at 10.969,-43.929 h1.78
  text "2" at 74.358,-43.929 h1.78
  text "3" at 137.588,-43.929 h1.78
  text "4" at 201.257,-43.929 h1.78
  text "5" at 264.731,-43.929 h1.78
  text "6" at 328.358,-43.929 h1.78
M10 Fab Notes:
  drawing of 173 lines, arcs and shapes, not listed
  text "DESIGN INFORMATION" at 306.578,145.669 h1.52
  text "MIN. TRACK WIDTH:" at 290.207,141.097 h1.52
  text "8" at 318.051,141.097 h1.52
  text "MIL" at 321.982,141.097 h1.52
  text "MIN. CLEARANCE:" at 290.207,137.744 h1.52
  text "0.2" at 316.527,137.744 h1.52
  text "mm" at 321.982,137.744 h1.52
  text "MIN. VIA PAD SIZE:" at 290.207,134.391 h1.52
  text "24" at 317.289,134.391 h1.52
  text "MIL" at 321.982,134.391 h1.52
  text "0.05mm (2MIL)" at 307.86,130.792 h1.52
  text "MINIMUM ANNULAR RING" at 281.844,130.683 h1.52
  text "EXTERNAL" at 325.843,130.683 h1.52
  text "PER" at 286.924,127.686 h1.52
  text "IPC-D-275 CLASS 2 LEVEL C" at 292.512,127.686 h1.52
  text "MIL, HOLES" at 330.313,124.834 h1.52
  text "+/-" at 320.345,124.816 h1.52
  text "+/-" at 342.036,124.816 h1.52
  text "REGISTRATION TOLERANCES:" at 281.844,124.689 h1.52
  text "METAL" at 312.318,124.689 h1.52
  text "5" at 326.954,124.689 h1.52
  text "3" at 348.112,124.689 h1.52
  text "MIL" at 351.065,124.689 h1.52
  text "+/-" at 342.036,121.818 h1.52
  text "HOLE SIZE TOLERANCE (UNLESS OTHERWISE SPECIFIED):" at 281.844,121.691 h1.52
  text "3" at 348.112,121.691 h1.52
  text "MIL" at 351.065,121.691 h1.52
  text "MATERIAL:" at 279.945,116.371 h1.52
  text "FR-4 High Tg" at 305.001,112.807 h1.52
  text "FR-408" at 290.639,112.589 h1.52
  text "OTHER" at 328.434,112.589 h1.52
  text "X" at 301.066,112.497 h1.52
  text "62 MIL (1.6mm) +/-10%" at 298.769,108.456 h1.52
  text "THICKNESS:" at 281.844,108.347 h1.52
  text "X" at 295.514,108.347 h1.52
  text "OTHER" at 331.405,108.347 h1.52
  text "TOLERANCE:" at 281.844,104.334 h1.52
  text "X" at 303.163,104.334 h1.52
  text "ANSI IPC-6012 TYPE 3 CLASS 2" at 307.911,104.334 h1.52
  text "OTHER +/-" at 307.91,100.372 h1.52
  text "BOW & TWIST:" at 281.844,96.384 h1.52
  text "X" at 303.163,96.384 h1.52
  text "ANSI IPC-6012 TYPE 3 CLASS 2" at 307.911,96.384 h1.52
  text "OTHER +/-" at 307.91,92.358 h1.52
  text "DRILLING:" at 279.945,88.84 h1.52
  text "REFERENCE:" at 281.844,85.868 h1.52
  text "X" at 298.309,85.868 h1.52
  text "AS SHOWN" at 303.059,85.868 h1.52
  text "X" at 321.195,85.868 h1.52
  text "NC_DRILL FILES" at 324.674,85.868 h1.52
  text "PTH COPPER THICKNESS:" at 281.844,81.855 h1.52
  text "X" at 310.552,81.855 h1.52
  text "20-30 um" at 314.032,81.855 h1.52
  text "OTHER" at 332.244,81.855 h1.52
  text "BOARD FINISH:" at 279.945,77.816 h1.52
  text "SILKSCREEN:" at 283.888,74.819 h1.52
  text "X" at 307.987,74.819 h1.52
  text "TOP" at 311.187,74.819 h1.52
  text "X" at 320.941,74.819 h1.52
  text "BOTTOM" at 324.166,74.819 h1.52
  text "SILKSCREEN COLOR:" at 283.888,70.577 h1.52
  text "X" at 307.96,70.577 h1.52
  text "WHITE" at 311.187,70.577 h1.52
  text "OTHER" at 324.166,70.577 h1.52
  text "X" at 311.288,66.534 h1.52
  text "GREEN" at 314.514,66.534 h1.52
  text "OTHER" at 330.212,66.534 h1.52
  text "SOLDER RESIST COLOR:" at 283.888,66.259 h1.52
  text "X" at 311.288,62.216 h1.52
  text "MATTE" at 314.514,62.216 h1.52
  text "SEMI-GLOSS" at 330.2,62.2 h1.52
  text "IMMERSION GOLD (ENIG)" at 306.894,57.427 h1.52
  text "ENEPIG" at 340.868,57.344 h1.52
  text "SURFACE FINISH:" at 279.945,57.319 h1.52
  text "X" at 302.146,57.319 h1.52
  text "IMM. TIN/SILVER OR EQUIV" at 288.315,53.331 h1.52
  text "OTHER" at 324.674,53.331 h1.52
  text "ARRAY/PANEL:" at 279.945,48.784 h1.52
  text "CUT AND TRIM PER M1 BOARD OUTLINE" at 306.894,48.675 h1.52
  text "N.C. ROUTE" at 306.894,44.822 h1.52
  text "X" at 324.141,44.822 h1.52
  text "V. SCORE" at 328.891,44.822 h1.52
  text "CERTIFICATION:" at 279.945,41.342 h1.52
  text "MATERIALS AND WORKMANSHIP FOR ALL PCBS" at 298.36,41.342 h1.52
  text "TO MEET OR EXCEED THE REQUIREMENTS OF:" at 298.36,38.853 h1.52
  text "X" at 288.873,35.386 h1.52
  text "ANSI IPC-A-600F CLASS ->" at 292.404,35.386 h1.52
  text "X" at 334.036,35.386 h1.52
  text "2" at 337.057,35.386 h1.52
  text "1" at 329.056,35.348 h1.52
  text "3" at 346.049,35.348 h1.52
  text "X" at 309.55,31.334 h1.52
  text "RoHS" at 313.029,31.334 h1.52
  text "OTHER" at 329.396,31.334 h1.52
  text "PER ORDER" at 339.482,31.334 h1.52
  text "ALL BOARDS MUST MEET OR EXCEED UL94-V0 REQUIREMENTS." at 280.645,27.127 h1.52
  text "PCB MUST BEAR THE UL94V-0 UL REGISTERED MATERIAL ID NUMBER" at 280.645,24.079 h1.52
  text "ADDITIONAL REQUIREMENTS:" at 279.945,19.676 h1.52
  text "MICROSECTION:" at 281.844,16.755 h1.52
  text "YES" at 304.85,16.755 h1.52
  text "REQUIRED" at 326.732,12.789 h1.52
  text "BARE BOARD ELEC. TEST:" at 281.844,12.716 h1.52
  text "NONE" at 315.01,12.716 h1.52
  text "X" at 323.506,12.716 h1.52
  text "PER ORDER" at 341.769,12.716 h1.52
  text ".Layer_Name" at 6.833,-33.642 h1.52
M11 Gerber Information:
  lines w0.254: -15.24,-35.463 152.4,-35.463 ; -15.24,-30.298 152.451,-30.298 ; -15.24,-25.133 -15.24,-40.627 86.487,-40.627 152.451,-40.627 152.451,-25.133 -15.227,-25.133 -15.227,-40.627 24.79,-40.627 ; 47.371,-40.627 47.371,-25.133 ; 79.553,-30.298 79.553,-25.133 ; 100.889,-30.298 100.889,-25.133 ; 116.688,-40.792 116.688,-35.64
  text "ALL ARTWORK VIEWED FROM TOP SIDE" at -13.627,-28.49 h1.52
  text "BOARD #:" at 49.276,-28.49 h1.52
  text ".PRJ_Number" at 63.132,-28.49 h1.52
  text "REV:" at 84.582,-28.49 h1.52
  text ".PCB_Rev" at 91.986,-28.49 h1.52
  text "SVN REV:" at 105.867,-28.49 h1.52
  text ".VersionControl_RevNumber" at 118.72,-28.49 h1.52
  text "LAYER NAME =" at -13.627,-33.642 h1.52
  text "TID #:" at 49.276,-33.655 h1.52
  text ".TID" at 63.132,-33.655 h1.52
  text "PLOT NAME =" at -13.627,-38.871 h1.52
  text ".plot_File_Name" at 6.833,-38.871 h1.52
  text "GENERATED    :" at 49.327,-38.871 h1.52
  text ".Print_Date" at 71.412,-38.871 h1.52
  text ".Print_Time" at 89.929,-38.871 h1.52
  text "TEXAS INSTRUMENTS" at 122.047,-38.871 h1.52
M12 Stackup:
  drawing of 191 lines, arcs and shapes, not listed
  text "Layer" at 240.852,187.046 h1.52
  text "Name" at 251.263,187.046 h1.52
  text "Material" at 274.879,187.046 h1.52
  text "Thickness" at 296.717,187.046 h1.52
  text "Constant" at 313.223,187.046 h1.52
  text "Board Layer Stack" at 327.697,187.046 h1.52
  text "1" at 240.852,183.998 h1.52
  text "Top Overlay" at 251.263,183.998 h1.52
  text "2" at 240.852,180.95 h1.52
  text "Top Solder" at 251.263,180.95 h1.52
  text "Solder Resist" at 274.879,180.95 h1.52
  text "0.40mil" at 296.717,180.95 h1.52
  text "3.5" at 313.223,180.95 h1.52
  text "3" at 240.852,177.902 h1.52
  text "Top Layer" at 251.263,177.902 h1.52
  text "Copper" at 274.879,177.902 h1.52
  text "1.40mil" at 296.717,177.902 h1.52
  text "4" at 240.852,174.854 h1.52
  text "Dielectric1" at 251.263,174.854 h1.52
  text "FR-4" at 274.879,174.854 h1.52
  text "59.20mil" at 296.717,174.854 h1.52
  text "4.8" at 313.223,174.854 h1.52
  text "5" at 240.852,171.806 h1.52
  text "Bottom Layer" at 251.263,171.806 h1.52
  text "Copper" at 274.879,171.806 h1.52
  text "1.40mil" at 296.717,171.806 h1.52
  text "6" at 240.852,168.758 h1.52
  text "Bottom Solder" at 251.263,168.758 h1.52
  text "Solder Resist" at 274.879,168.758 h1.52
  text "0.40mil" at 296.717,168.758 h1.52
  text "3.5" at 313.223,168.758 h1.52
  text "7" at 240.852,165.71 h1.52
  text "Bottom Overlay" at 251.263,165.71 h1.52
M13 Component Bodies Top:
  text ".Layer_Name" at 6.833,-33.642 h1.52
M14 Component Bodies Bottom:
  text ".Layer_Name" at 6.833,-33.642 h1.52
M15 Courtyards Top:
  text ".Layer_Name" at 6.833,-33.642 h1.52
M16 Courtyards Bottom:
  text ".Layer_Name" at 6.833,-33.642 h1.52
Drill Drawing:
  circle w0.254: c128.415,64.812 r0.702
  lines w0.254: 127.713,56.04 129.117,56.04 128.415,54.637 127.713,56.04 ; 127.713,57.795 129.117,57.795 129.117,59.198 127.713,59.198 127.713,57.795 ; 127.713,61.303 128.064,61.303 128.064,60.952 128.766,60.952 128.766,61.303 129.117,61.303 129.117,62.005 128.766,62.005 128.766,62.356 128.064,62.356 128.064,62.005 127.713,62.005 127.713,61.303 ; 127.713,67.268 127.713,67.619 128.064,67.969 127.713,68.32 127.713,68.671 128.064,68.671 128.415,68.32 128.766,68.671 129.117,68.671 129.117,68.32 128.766,67.969 129.117,67.619 129.117,67.268 128.766,67.268 128.415,67.619 128.064,67.268 127.713,67.268 ; 127.713,70.425 128.415,70.776 129.117,70.425 128.766,71.127 129.117,71.829 128.415,71.478 127.713,71.829 128.064,71.127 127.713,70.425
  lines w0.305: 126.441,53.69 208.521,53.69 ; 126.441,72.636 208.521,72.636 ; 135.023,50.532 135.023,75.794 ; 143.456,50.532 143.456,75.794 ; 159.624,50.532 159.624,75.794 ; 166.207,50.532 166.207,75.794 ; 175.736,50.532 175.736,75.794 ; 194.134,50.532 194.134,75.794 ; 126.441,50.532 208.521,50.532 208.521,75.794 126.441,75.794 126.441,50.532
  text "Symbol" at 128.336,73.583 h1.83
  text "Quantity" at 135.97,73.583 h1.83
  text "Finished Hole Size" at 144.403,73.583 h1.83
  text "Plated" at 160.572,73.583 h1.83
  text "Hole Type" at 167.154,73.583 h1.83
  text "Drill Layer Pair" at 176.683,73.583 h1.83
  text "Hole Tolerance" at 195.081,73.583 h1.83
  text "5" at 135.97,70.425 h1.52
  text "7.87mil (0.200mm)" at 144.403,70.425 h1.52
  text "PTH" at 160.572,70.425 h1.52
  text "Round" at 167.154,70.425 h1.52
  text "Top Layer - Bottom Layer" at 176.683,70.425 h1.52
  text "17" at 135.97,67.268 h1.52
  text "8.00mil (0.203mm)" at 144.403,67.268 h1.52
  text "PTH" at 160.572,67.268 h1.52
  text "Round" at 167.154,67.268 h1.52
  text "Top Layer - Bottom Layer" at 176.683,67.268 h1.52
  text "23" at 135.97,64.11 h1.52
  text "16.00mil (0.406mm)" at 144.403,64.11 h1.52
  text "PTH" at 160.572,64.11 h1.52
  text "Round" at 167.154,64.11 h1.52
  text "Top Layer - Bottom Layer" at 176.683,64.11 h1.52
  text "7" at 135.97,60.952 h1.52
  text "27.95mil (0.710mm)" at 144.403,60.952 h1.52
  text "PTH" at 160.572,60.952 h1.52
  text "Round" at 167.154,60.952 h1.52
  text "Top Layer - Bottom Layer" at 176.683,60.952 h1.52
  text "8" at 135.97,57.795 h1.52
  text "29.53mil (0.750mm)" at 144.403,57.795 h1.52
  text "PTH" at 160.572,57.795 h1.52
  text "Round" at 167.154,57.795 h1.52
  text "Top Layer - Bottom Layer" at 176.683,57.795 h1.52
  text "18" at 135.97,54.637 h1.52
  text "39.37mil (1.000mm)" at 144.403,54.637 h1.52
  text "PTH" at 160.572,54.637 h1.52
  text "Round" at 167.154,54.637 h1.52
  text "Top Layer - Bottom Layer" at 176.683,54.637 h1.52
  text "78 Total" at 135.97,51.479 h1.52
  text ".Layer_Name" at 6.833,-33.642 h1.52
M17 Embedded Cavity:
  text ".Layer_Name" at 6.833,-33.642 h1.52
M18 Embedded Assembly:
  text ".Layer_Name" at 6.833,-33.642 h1.52
M19 Embedded Keepout:
  text ".Layer_Name" at 6.833,-33.642 h1.52

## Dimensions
-7.823,-21.996 to 17.577,-21.996 on M2 Board Dimensions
